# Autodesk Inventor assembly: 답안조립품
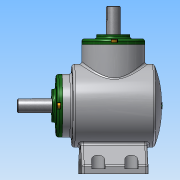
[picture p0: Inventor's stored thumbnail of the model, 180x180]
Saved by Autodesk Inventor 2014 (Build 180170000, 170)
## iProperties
Created: 2017-04
Part Number: 답안조립품
Document SubType Name: Assembly
Designer: NET
Author: NET
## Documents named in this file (14)
- C:\Users\NET\Desktop\470407V1015\답안조립품.iam
- C:\Users\NET\Desktop\470407V1015\본체.ipt
- C:\Users\NET\Desktop\470407V1015\베어링 6203.ipt
- C:\Users\NET\Desktop\470407V1015\커버.ipt
- C:\Users\NET\Desktop\470407V1015\메인 축.ipt
- 메인 축.ipt
- C:\Users\NET\Desktop\470407V1015\메인 베벨기어.ipt
- C:\Users\NET\Desktop\470407V1015\키 5x5.ipt
- C:\Users\NET\Desktop\470407V1015\서브 축.ipt
- 서브 축.ipt
- C:\Users\NET\Desktop\470407V1015\서브 베벨기어.ipt
- C:\Users\NET\Desktop\470407V1015\키 4x4.ipt
- C:\Users\NET\Desktop\470407V1015\볼트 M4.ipt
- C:\Users\NET\Desktop\470407V1015\오일실 17 32 8.ipt
